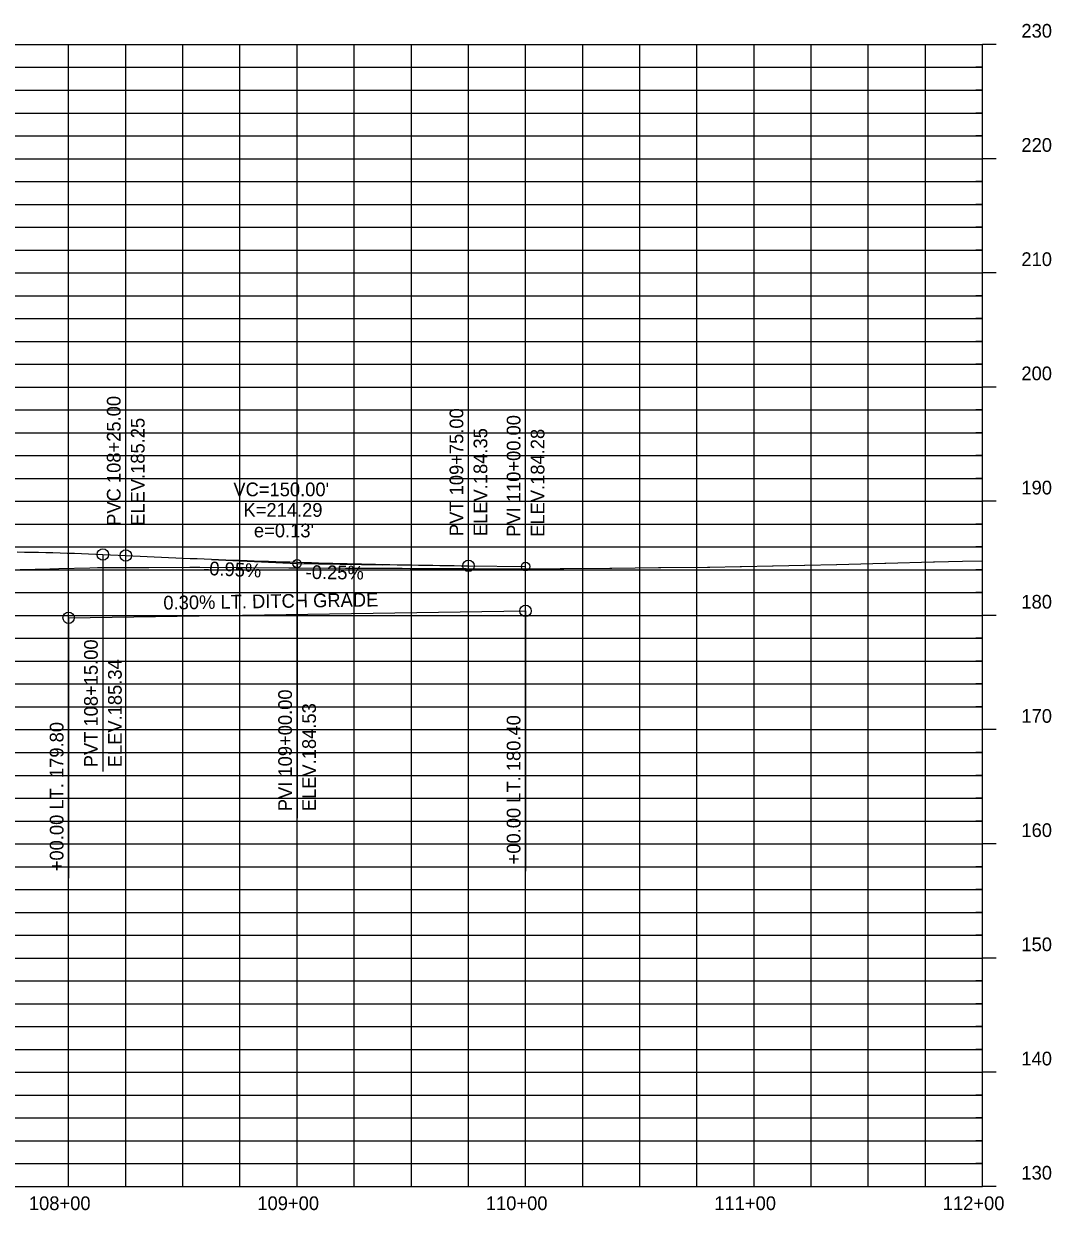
# Model space of a CAD drawing. Extents: x 1409239 to 1412142, y 1838831 to 1842626.
# Drawn here: x 1411693 to 1412142, y 1842106 to 1842626 of the extents above; entities that cross this region are included whole.
import ezdxf

# ---------------------------------------------------------------- set-up
doc = ezdxf.new("R2010")
doc.units = 0
for name, color, linetype in [('R_Axis_Annotation', 7, 'Continuous'), ('R_Exist Surface', 7, 'Continuous'), ('R_Grid', 7, 'Continuous'), ('R_Grid Annot', 7, 'Continuous'), ('R_Grid_Minor', 7, 'Continuous'), ('R_Vert Alg', 7, 'Continuous'), ('R_Vert Alg Annot', 7, 'Continuous')]:
    doc.layers.add(name, color=color, linetype=linetype)

msp = doc.modelspace()

# ---------------------------------------------------------------- linework, layer by layer
at = {"layer": 'R_Exist Surface'}
msp.add_lwpolyline([(1411691.21, 1842386.99), (1411704.14, 1842387.25), (1411708.1, 1842387.39), (1411721.58, 1842387.66), (1411725, 1842387.78), (1411742.93, 1842387.83), (1411747.42, 1842387.84), (1411765.35, 1842387.89), (1411769.85, 1842387.9), (1411785.86, 1842387.81), (1411789.25, 1842387.79), (1411792.55, 1842387.77), (1411808.69, 1842387.68), (1411812.65, 1842387.64), (1411833.54, 1842387.57), (1411837.21, 1842387.53), (1411858.4, 1842387.46), (1411861.77, 1842387.43), (1411883.25, 1842387.36), (1411886.32, 1842387.33), (1411908.1, 1842387.25), (1411927.42, 1842387.4), (1411929.08, 1842387.43), (1411949.18, 1842387.57), (1411950.04, 1842387.58), (1411970.54, 1842387.77), (1411971.49, 1842387.76), (1411991.91, 1842387.94), (1411992.93, 1842387.93), (1412006.34, 1842388.2), (1412006.84, 1842388.21), (1412020.4, 1842388.49), (1412020.75, 1842388.49), (1412034.46, 1842388.77), (1412034.65, 1842388.78), (1412048.51, 1842389.06), (1412048.55, 1842389.06), (1412069.66, 1842389.65), (1412069.98, 1842389.66), (1412090.83, 1842390.24), (1412091.4, 1842390.25), (1412103.61, 1842390.54), (1412112.15, 1842390.68), (1412112.35, 1842390.68)], dxfattribs=at)
at = {"layer": 'R_Grid'}
for p, q in [((1410912.35, 1842616.81), (1412112.35, 1842616.81)), ((1410912.35, 1842616.81), (1412112.35, 1842616.81)), ((1411712.35, 1842116.81), (1411712.35, 1842616.81)), ((1411812.35, 1842116.81), (1411812.35, 1842616.81)), ((1411912.35, 1842116.81), (1411912.35, 1842616.81)), ((1412012.35, 1842116.81), (1412012.35, 1842616.81)), ((1412112.35, 1842116.81), (1412112.35, 1842616.81)), ((1410912.35, 1842566.81), (1412112.35, 1842566.81)), ((1410912.35, 1842516.81), (1412112.35, 1842516.81)), ((1410912.35, 1842466.81), (1412112.35, 1842466.81)), ((1410912.35, 1842416.81), (1412112.35, 1842416.81)), ((1410912.35, 1842366.81), (1412112.35, 1842366.81)), ((1410912.35, 1842316.81), (1412112.35, 1842316.81)), ((1410912.35, 1842266.81), (1412112.35, 1842266.81)), ((1410912.35, 1842216.81), (1412112.35, 1842216.81)), ((1410912.35, 1842166.81), (1412112.35, 1842166.81)), ((1410912.35, 1842116.81), (1412112.35, 1842116.81))]:
    msp.add_line(p, q, dxfattribs=at)
at = {"layer": 'R_Grid Annot'}
for p, q in [((1412118.35, 1842616.81), (1412112.35, 1842616.81)), ((1412118.35, 1842616.81), (1412112.35, 1842616.81)), ((1412112.35, 1842606.81), (1412109.35, 1842606.81)), ((1412112.35, 1842596.81), (1412109.35, 1842596.81)), ((1412112.35, 1842586.81), (1412109.35, 1842586.81)), ((1412112.35, 1842576.81), (1412109.35, 1842576.81)), ((1412118.35, 1842566.81), (1412112.35, 1842566.81)), ((1412112.35, 1842556.81), (1412109.35, 1842556.81)), ((1412112.35, 1842546.81), (1412109.35, 1842546.81)), ((1412112.35, 1842536.81), (1412109.35, 1842536.81)), ((1412112.35, 1842526.81), (1412109.35, 1842526.81)), ((1412118.35, 1842516.81), (1412112.35, 1842516.81)), ((1412112.35, 1842506.81), (1412109.35, 1842506.81)), ((1412112.35, 1842496.81), (1412109.35, 1842496.81)), ((1412112.35, 1842486.81), (1412109.35, 1842486.81)), ((1412112.35, 1842476.81), (1412109.35, 1842476.81)), ((1412118.35, 1842466.81), (1412112.35, 1842466.81)), ((1412112.35, 1842456.81), (1412109.35, 1842456.81)), ((1412112.35, 1842446.81), (1412109.35, 1842446.81)), ((1412112.35, 1842436.81), (1412109.35, 1842436.81)), ((1412112.35, 1842426.81), (1412109.35, 1842426.81)), ((1412118.35, 1842416.81), (1412112.35, 1842416.81)), ((1412112.35, 1842406.81), (1412109.35, 1842406.81)), ((1412112.35, 1842396.81), (1412109.35, 1842396.81)), ((1412112.35, 1842386.81), (1412109.35, 1842386.81)), ((1412112.35, 1842376.81), (1412109.35, 1842376.81)), ((1412118.35, 1842366.81), (1412112.35, 1842366.81)), ((1412112.35, 1842356.81), (1412109.35, 1842356.81)), ((1412112.35, 1842346.81), (1412109.35, 1842346.81)), ((1412112.35, 1842336.81), (1412109.35, 1842336.81)), ((1412112.35, 1842326.81), (1412109.35, 1842326.81)), ((1412118.35, 1842316.81), (1412112.35, 1842316.81)), ((1412112.35, 1842306.81), (1412109.35, 1842306.81)), ((1412112.35, 1842296.81), (1412109.35, 1842296.81)), ((1412112.35, 1842286.81), (1412109.35, 1842286.81)), ((1412112.35, 1842276.81), (1412109.35, 1842276.81)), ((1412118.35, 1842266.81), (1412112.35, 1842266.81)), ((1412112.35, 1842256.81), (1412109.35, 1842256.81)), ((1412112.35, 1842246.81), (1412109.35, 1842246.81)), ((1412112.35, 1842236.81), (1412109.35, 1842236.81)), ((1412112.35, 1842226.81), (1412109.35, 1842226.81)), ((1412118.35, 1842216.81), (1412112.35, 1842216.81)), ((1412112.35, 1842206.81), (1412109.35, 1842206.81)), ((1412112.35, 1842196.81), (1412109.35, 1842196.81)), ((1412112.35, 1842186.81), (1412109.35, 1842186.81)), ((1412112.35, 1842176.81), (1412109.35, 1842176.81)), ((1412118.35, 1842166.81), (1412112.35, 1842166.81)), ((1412112.35, 1842156.81), (1412109.35, 1842156.81)), ((1412112.35, 1842146.81), (1412109.35, 1842146.81)), ((1412112.35, 1842136.81), (1412109.35, 1842136.81)), ((1412112.35, 1842126.81), (1412109.35, 1842126.81)), ((1412118.35, 1842116.81), (1412112.35, 1842116.81))]:
    msp.add_line(p, q, dxfattribs=at)
at = {"layer": 'R_Grid_Minor'}
for p, q in [((1411737.35, 1842116.81), (1411737.35, 1842616.81)), ((1411762.35, 1842116.81), (1411762.35, 1842616.81)), ((1411787.35, 1842116.81), (1411787.35, 1842616.81)), ((1411837.35, 1842116.81), (1411837.35, 1842616.81)), ((1411862.35, 1842116.81), (1411862.35, 1842616.81)), ((1411887.35, 1842116.81), (1411887.35, 1842616.81)), ((1411937.35, 1842116.81), (1411937.35, 1842616.81)), ((1411962.35, 1842116.81), (1411962.35, 1842616.81)), ((1411987.35, 1842116.81), (1411987.35, 1842616.81)), ((1412037.35, 1842116.81), (1412037.35, 1842616.81)), ((1412062.35, 1842116.81), (1412062.35, 1842616.81)), ((1412087.35, 1842116.81), (1412087.35, 1842616.81)), ((1410912.35, 1842606.81), (1412112.35, 1842606.81)), ((1410912.35, 1842596.81), (1412112.35, 1842596.81)), ((1410912.35, 1842586.81), (1412112.35, 1842586.81)), ((1410912.35, 1842576.81), (1412112.35, 1842576.81)), ((1410912.35, 1842556.81), (1412112.35, 1842556.81)), ((1410912.35, 1842546.81), (1412112.35, 1842546.81)), ((1410912.35, 1842536.81), (1412112.35, 1842536.81)), ((1410912.35, 1842526.81), (1412112.35, 1842526.81)), ((1410912.35, 1842506.81), (1412112.35, 1842506.81)), ((1410912.35, 1842496.81), (1412112.35, 1842496.81)), ((1410912.35, 1842486.81), (1412112.35, 1842486.81)), ((1410912.35, 1842476.81), (1412112.35, 1842476.81)), ((1410912.35, 1842456.81), (1412112.35, 1842456.81)), ((1410912.35, 1842446.81), (1412112.35, 1842446.81)), ((1410912.35, 1842436.81), (1412112.35, 1842436.81)), ((1410912.35, 1842426.81), (1412112.35, 1842426.81)), ((1410912.35, 1842406.81), (1412112.35, 1842406.81)), ((1410912.35, 1842396.81), (1412112.35, 1842396.81)), ((1410912.35, 1842386.81), (1412112.35, 1842386.81)), ((1410912.35, 1842376.81), (1412112.35, 1842376.81)), ((1410912.35, 1842356.81), (1412112.35, 1842356.81)), ((1410912.35, 1842346.81), (1412112.35, 1842346.81)), ((1410912.35, 1842336.81), (1412112.35, 1842336.81)), ((1410912.35, 1842326.81), (1412112.35, 1842326.81)), ((1410912.35, 1842306.81), (1412112.35, 1842306.81)), ((1410912.35, 1842296.81), (1412112.35, 1842296.81)), ((1410912.35, 1842286.81), (1412112.35, 1842286.81)), ((1410912.35, 1842276.81), (1412112.35, 1842276.81)), ((1410912.35, 1842256.81), (1412112.35, 1842256.81)), ((1410912.35, 1842246.81), (1412112.35, 1842246.81)), ((1410912.35, 1842236.81), (1412112.35, 1842236.81)), ((1410912.35, 1842226.81), (1412112.35, 1842226.81)), ((1410912.35, 1842206.81), (1412112.35, 1842206.81)), ((1410912.35, 1842196.81), (1412112.35, 1842196.81)), ((1410912.35, 1842186.81), (1412112.35, 1842186.81)), ((1410912.35, 1842176.81), (1412112.35, 1842176.81)), ((1410912.35, 1842156.81), (1412112.35, 1842156.81)), ((1410912.35, 1842146.81), (1412112.35, 1842146.81)), ((1410912.35, 1842136.81), (1412112.35, 1842136.81)), ((1410912.35, 1842126.81), (1412112.35, 1842126.81))]:
    msp.add_line(p, q, dxfattribs=at)
at = {"layer": 'R_Vert Alg'}
for p, q in [((1411727.35, 1842393.52), (1411737.35, 1842393.05)), ((1411887.35, 1842388.55), (1411912.35, 1842388.24)), ((1411712.35, 1842365.81), (1411912.35, 1842368.81))]:
    msp.add_line(p, q, dxfattribs=at)
for points in [[(1411689.85, 1842394.61), (1411692.98, 1842394.57), (1411696.1, 1842394.53), (1411699.23, 1842394.47), (1411702.35, 1842394.4), (1411705.48, 1842394.33), (1411708.6, 1842394.24), (1411711.73, 1842394.15), (1411714.85, 1842394.04), (1411717.98, 1842393.93), (1411721.1, 1842393.8), (1411724.23, 1842393.67), (1411727.35, 1842393.52)], [(1411737.35, 1842393.05), (1411740.48, 1842392.9), (1411743.6, 1842392.76), (1411746.73, 1842392.61), (1411749.85, 1842392.47), (1411752.98, 1842392.33), (1411756.1, 1842392.2), (1411759.23, 1842392.06), (1411762.35, 1842391.93), (1411765.48, 1842391.8), (1411768.6, 1842391.68), (1411771.73, 1842391.55), (1411774.85, 1842391.43), (1411777.98, 1842391.31), (1411781.1, 1842391.19), (1411784.23, 1842391.08), (1411787.35, 1842390.96), (1411790.48, 1842390.85), (1411793.6, 1842390.75), (1411796.73, 1842390.64), (1411799.85, 1842390.53), (1411802.98, 1842390.43), (1411806.1, 1842390.33), (1411809.23, 1842390.24), (1411815.48, 1842390.05), (1411818.6, 1842389.96), (1411821.73, 1842389.87), (1411824.85, 1842389.78), (1411827.98, 1842389.7), (1411831.1, 1842389.62), (1411834.23, 1842389.54), (1411837.35, 1842389.46), (1411840.48, 1842389.39), (1411843.6, 1842389.32), (1411846.73, 1842389.25), (1411849.85, 1842389.18), (1411852.98, 1842389.12), (1411856.1, 1842389.05), (1411859.23, 1842388.99), (1411862.35, 1842388.93), (1411865.48, 1842388.88), (1411868.6, 1842388.82), (1411871.73, 1842388.77), (1411874.85, 1842388.72), (1411877.98, 1842388.68), (1411881.1, 1842388.63), (1411884.23, 1842388.59), (1411887.35, 1842388.55)]]:
    msp.add_lwpolyline(points, dxfattribs=at)
at = {"layer": 'R_Vert Alg Annot'}
for p, q in [((1411737.35, 1842403.05), (1411737.35, 1842487.05)), ((1411887.35, 1842398.55), (1411887.35, 1842482.55)), ((1411912.35, 1842398.24), (1411912.35, 1842482.24)), ((1411737.35, 1842393.05), (1411737.35, 1842403.05)), ((1411887.35, 1842388.55), (1411887.35, 1842398.55)), ((1411912.35, 1842388.24), (1411912.35, 1842398.24)), ((1411727.35, 1842393.52), (1411727.35, 1842383.52)), ((1411774.85, 1842391.27), (1411812.35, 1842389.49)), ((1411812.35, 1842389.49), (1411849.85, 1842389.02)), ((1411812.35, 1842389.49), (1411812.35, 1842362.11)), ((1411727.35, 1842383.52), (1411727.35, 1842298.5)), ((1411712.35, 1842365.81), (1411712.35, 1842335.81)), ((1411912.35, 1842368.81), (1411912.35, 1842338.81)), ((1411812.35, 1842362.11), (1411812.35, 1842278.11)), ((1411912.35, 1842338.81), (1411912.35, 1842254.81)), ((1411712.35, 1842335.81), (1411712.35, 1842251.81))]:
    msp.add_line(p, q, dxfattribs=at)
for centre, radius in [((1411727.35, 1842393.52), 2.5), ((1411737.35, 1842393.05), 2.5), ((1411812.35, 1842389.49), 1.85), ((1411887.35, 1842388.55), 2.5), ((1411912.35, 1842388.24), 1.85), ((1411912.35, 1842368.81), 2.5), ((1411712.35, 1842365.81), 2.5)]:
    msp.add_circle(centre, radius, dxfattribs=at)

# ---------------------------------------------------------------- texts
at = {"layer": 'R_Axis_Annotation'}
for s, p in [('230', (1412129.36, 1842619.81)), ('230', (1412129.36, 1842619.81)), ('220', (1412129.36, 1842569.81)), ('210', (1412129.36, 1842519.81)), ('200', (1412129.36, 1842469.81)), ('190', (1412129.36, 1842419.81)), ('180', (1412129.36, 1842369.81)), ('170', (1412129.36, 1842319.81)), ('160', (1412129.36, 1842269.81)), ('150', (1412129.36, 1842219.81)), ('140', (1412129.36, 1842169.81)), ('130', (1412129.36, 1842119.81)), ('108+00', (1411694.95, 1842106.46)), ('109+00', (1411794.95, 1842106.46)), ('110+00', (1411894.95, 1842106.46)), ('111+00', (1411994.95, 1842106.46)), ('112+00', (1412094.95, 1842106.46))]:
    msp.add_text(s, height=6, dxfattribs=at).set_placement(p)
at = {"layer": 'R_Vert Alg Annot'}
for s, rotation, p in [('PVC 108+25.00', 90, (1411735.1, 1842406.05)), ('ELEV.185.25', 90, (1411745.6, 1842406.05)), ('PVT 109+75.00', 90, (1411885.1, 1842401.55)), ('PVI 110+00.00', 90, (1411910.1, 1842401.24)), ('ELEV.184.35', 90, (1411895.6, 1842401.55)), ('ELEV.184.28', 90, (1411920.6, 1842401.24)), ('-0.95%', 357.2805, (1411771.14, 1842384.59)), ('-0.25%', 359.2838, (1411816.07, 1842382.83)), ('0.30% LT. DITCH GRADE', 0.8594, (1411753.86, 1842369.37)), ('PVT 108+15.00', 90, (1411725.1, 1842300.34)), ('ELEV.185.34', 90, (1411735.6, 1842300.34)), ('PVI 109+00.00', 90, (1411810.1, 1842281.11)), ('ELEV.184.53', 90, (1411820.6, 1842281.11)), ('+00.00 LT. 180.40', 90, (1411910.1, 1842257.81)), ('+00.00 LT. 179.80', 90, (1411710.1, 1842254.81))]:
    msp.add_text(s, height=6, rotation=rotation, dxfattribs=at).set_placement(p)
for s, p in [("VC=150.00'", (1411784.45, 1842419.01)), ('K=214.29', (1411788.88, 1842410.01)), ("e=0.13'", (1411793.45, 1842401.01))]:
    msp.add_text(s, height=6, dxfattribs=at).set_placement(p)

doc.saveas('drawing.dxf')
